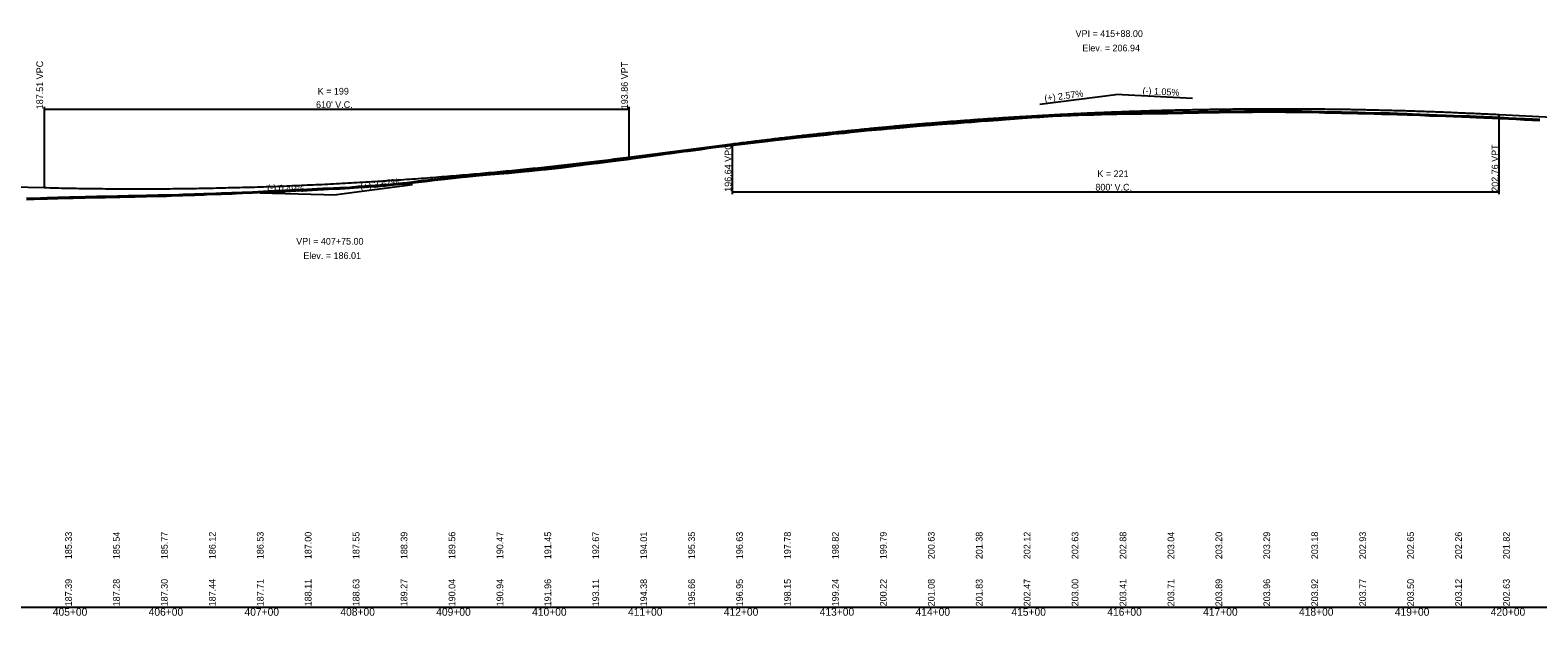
# Model space of a CAD drawing. Extents: x 1876258 to 1932803, y 754739 to 837911.
# Drawn here: x 1918819 to 1920391, y 827954 to 828565 of the extents above; entities that cross this region are included whole.
import ezdxf

# ---------------------------------------------------------------- set-up
doc = ezdxf.new("R2010")
doc.units = 0
for name, color, linetype in [('RD_DDB_GradeTX', 7, 'Continuous'), ('RD_DDB_Profile_EX', 7, 'Continuous'), ('RD_DDB_Profile_Lbl', 7, 'Continuous'), ('RD_DDB_Profile_PR', 7, 'Continuous'), ('RD_DDB_StaTX', 7, 'Continuous'), ('RD_DDB_StripGrade', 7, 'Continuous'), ('RD_DDB_VCLbl', 7, 'Continuous'), ('RD_GPK_Profile_Cell', 7, 'Continuous'), ('RD_Sketch1', 7, 'Continuous')]:
    doc.layers.add(name, color=color, linetype=linetype)

msp = doc.modelspace()

# ---------------------------------------------------------------- linework, layer by layer
at = {"layer": 'RD_DDB_GradeTX'}
for p, q in [((1919871.7, 828487.3), (1919951.1, 828497.5)), ((1920031, 828493.3), (1919951.1, 828497.5)), ((1919058.1, 828394.8), (1919138.1, 828392.9)), ((1919217.4, 828403.1), (1919138.1, 828392.9))]:
    msp.add_line(p, q, dxfattribs=at)
at = {"layer": 'RD_DDB_Profile_EX'}
for points in [[(1919426.8, 828428), (1919429.5, 828428.3), (1919443.7, 828430.2), (1919447.8, 828430.7), (1919460.7, 828432.5), (1919466, 828433.3), (1919478.1, 828435), (1919482.4, 828435.5), (1919486.2, 828436), (1919500.4, 828438), (1919504.9, 828438.5), (1919518.4, 828440.2), (1919526.1, 828441.4), (1919531.2, 828442.1), (1919543.6, 828443.6), (1919549.3, 828444.3), (1919561.3, 828445.8), (1919567.3, 828446.4), (1919578.9, 828447.8), (1919585.4, 828448.6), (1919596.1, 828449.9), (1919603, 828450.6), (1919614.4, 828451.8), (1919621.3, 828452.6), (1919632.2, 828453.7), (1919639.2, 828454.5), (1919649.9, 828455.5), (1919657.1, 828456.3), (1919667.7, 828457.3), (1919675, 828458.1), (1919685.4, 828459.1), (1919691.9, 828459.8), (1919701.4, 828460.7), (1919706.2, 828461.1), (1919712.5, 828461.7), (1919722.1, 828462.5), (1919729.6, 828463.1), (1919739.7, 828464.1), (1919747.2, 828464.7), (1919757.4, 828465.6), (1919765.1, 828466.1), (1919775.1, 828466.8), (1919782.8, 828467.4), (1919792.9, 828468.2), (1919800.4, 828468.7), (1919810.6, 828469.5), (1919818.2, 828470.1), (1919828.4, 828470.8), (1919836, 828471.5), (1919845.9, 828472.2), (1919853.7, 828472.8), (1919863.6, 828473.4), (1919871.8, 828474), (1919880.6, 828474.5), (1919885.5, 828474.8), (1919894.4, 828475.2), (1919904.1, 828475.7), (1919912, 828475.9), (1919920.8, 828476.2), (1919928.2, 828476.4), (1919936.1, 828476.7), (1919943, 828476.9), (1919952.3, 828477.1), (1919960.5, 828477.2), (1919969.9, 828477.3), (1919978.4, 828477.4), (1919987.6, 828477.5), (1919995.6, 828477.6), (1920005.2, 828477.8), (1920011.3, 828478), (1920020.9, 828478.1), (1920029.6, 828478.3), (1920037.4, 828478.5), (1920045.1, 828478.6), (1920051, 828478.6), (1920059, 828478.7), (1920067.3, 828478.9), (1920074.8, 828479), (1920085.5, 828479.2), (1920093.7, 828479.2), (1920102.7, 828479.3), (1920110.9, 828479.3), (1920119.9, 828479.3), (1920128.1, 828479.2), (1920137.1, 828479.1), (1920145.3, 828479), (1920155.2, 828478.9), (1920163.3, 828478.7), (1920169.3, 828478.5), (1920177.4, 828478.3), (1920186.4, 828478.1), (1920194.6, 828477.9), (1920203.7, 828477.7), (1920211.6, 828477.5), (1920220.6, 828477.3), (1920228.5, 828477.1), (1920236.6, 828476.9), (1920245.1, 828476.6), (1920254.9, 828476.3), (1920260.5, 828476.2), (1920268.6, 828475.8)], [(1920268.6, 828475.8), (1920278.4, 828475.4), (1920286.4, 828475.1), (1920295.3, 828474.8), (1920303.4, 828474.4), (1920312.2, 828474.1), (1920320.3, 828473.8), (1920326.9, 828473.6), (1920335.1, 828473.2), (1920343.8, 828472.8), (1920351.9, 828472.4), (1920360.7, 828472), (1920368.7, 828471.6), (1920377.6, 828471.2), (1920385.6, 828470.7), (1920393.3, 828470.3)], [(1918814.7, 828388), (1918822.9, 828388.2), (1918829.3, 828388.5), (1918836.7, 828388.7), (1918844.1, 828388.9), (1918847.6, 828389), (1918856.2, 828389.2), (1918859.5, 828389.4), (1918863.5, 828389.4), (1918871.9, 828389.6), (1918876, 828389.8), (1918884.6, 828389.9), (1918888.4, 828390.1), (1918896.7, 828390.2), (1918901.3, 828390.3), (1918909.8, 828390.5), (1918912.3, 828390.5), (1918920.8, 828390.7), (1918924.6, 828390.8), (1918927.7, 828390.8), (1918936.3, 828391), (1918939.8, 828391.1), (1918948.3, 828391.3), (1918952.2, 828391.4), (1918960.7, 828391.6), (1918965.7, 828391.7), (1918973.8, 828392), (1918977.9, 828392.2), (1918986.6, 828392.4), (1918990.2, 828392.6), (1918999.6, 828392.9), (1919002.8, 828393.1), (1919012.3, 828393.4), (1919018.2, 828393.6), (1919029.2, 828394), (1919033.6, 828394.1), (1919039.6, 828394.4), (1919050.6, 828394.9), (1919056.5, 828395.2), (1919067.5, 828395.6), (1919073.4, 828395.9), (1919084.3, 828396.4), (1919090.5, 828396.6), (1919101.3, 828397.2), (1919107.4, 828397.5), (1919118.2, 828398.1), (1919124.5, 828398.4), (1919135.1, 828399), (1919141.5, 828399.2), (1919152, 828399.7), (1919160.9, 828400.4), (1919167.5, 828400.8), (1919171.7, 828401.2), (1919178.7, 828401.6), (1919188.9, 828402.2), (1919193.9, 828402.8), (1919204, 828403.8), (1919207.4, 828404.2), (1919209.1, 828404.3), (1919217.4, 828405.2), (1919223.7, 828406.1), (1919233.5, 828407.1), (1919240.5, 828408), (1919251.2, 828409.3), (1919257.2, 828410), (1919269.1, 828411.2), (1919273.9, 828411.6), (1919287, 828412.9), (1919290.7, 828413.2), (1919298.7, 828413.9), (1919307.9, 828414.7), (1919317.9, 828415.5), (1919324.2, 828416), (1919334.4, 828417), (1919339.1, 828417.6), (1919352.1, 828418.9), (1919356.5, 828419.3), (1919372.4, 828421.1), (1919375, 828421.4), (1919377.6, 828421.7), (1919392.9, 828423.7), (1919393.5, 828423.8), (1919397.9, 828424.3), (1919409.9, 828425.8), (1919411.1, 828425.9), (1919426.8, 828428)]]:
    msp.add_lwpolyline(points, dxfattribs=at)
at = {"layer": 'RD_DDB_Profile_PR'}
for p, q in [((1920351.1, 828476.6), (1920799.1, 828453.2)), ((1919443.1, 828432.1), (1919551.1, 828446)), ((1917863.2, 828424.2), (1918833.1, 828400.4))]:
    msp.add_line(p, q, dxfattribs=at)
for points in [[(1919551.1, 828446), (1919567.1, 828448), (1919583.1, 828450), (1919599.1, 828451.9), (1919615.1, 828453.8), (1919631.1, 828455.6), (1919647.1, 828457.3), (1919663.1, 828459), (1919679.1, 828460.6), (1919695.1, 828462.2), (1919711.1, 828463.7), (1919727.1, 828465.2), (1919743.1, 828466.6), (1919759.1, 828467.9), (1919775.1, 828469.2), (1919791.1, 828470.4), (1919807.1, 828471.6), (1919823.1, 828472.7), (1919839.1, 828473.7), (1919855.1, 828474.7), (1919871.1, 828475.6), (1919887.1, 828476.5), (1919903.1, 828477.3), (1919919.1, 828478.1), (1919935.1, 828478.8), (1919951.1, 828479.4), (1919967.1, 828480), (1919983.1, 828480.5), (1919999.1, 828481), (1920015.1, 828481.4), (1920031.1, 828481.7), (1920047.1, 828482), (1920063.1, 828482.3), (1920079.1, 828482.4), (1920095.1, 828482.6), (1920111.1, 828482.6), (1920127.1, 828482.6), (1920143.1, 828482.6), (1920159.1, 828482.5), (1920175.1, 828482.3), (1920191.1, 828482.1), (1920207.1, 828481.8), (1920223.1, 828481.4), (1920239.1, 828481), (1920255.1, 828480.6), (1920271.1, 828480), (1920287.1, 828479.5), (1920303.1, 828478.8), (1920319.1, 828478.1), (1920335.1, 828477.4), (1920351.1, 828476.6)], [(1918833.1, 828400.4), (1918845.3, 828400.1), (1918857.5, 828399.8), (1918869.7, 828399.6), (1918881.9, 828399.5), (1918894.1, 828399.3), (1918906.3, 828399.2), (1918918.5, 828399.2), (1918930.7, 828399.2), (1918942.9, 828399.2), (1918955.1, 828399.2), (1918967.3, 828399.3), (1918979.5, 828399.5), (1918991.7, 828399.6), (1919003.9, 828399.8), (1919016.1, 828400.1), (1919028.3, 828400.4), (1919040.5, 828400.7), (1919052.7, 828401), (1919064.9, 828401.4), (1919077.1, 828401.8), (1919089.3, 828402.3), (1919101.5, 828402.8), (1919113.7, 828403.4), (1919125.9, 828403.9), (1919138.1, 828404.6), (1919150.3, 828405.2), (1919162.5, 828405.9), (1919174.7, 828406.6), (1919186.9, 828407.4), (1919199.1, 828408.2), (1919211.3, 828409), (1919223.5, 828409.9), (1919235.7, 828410.8), (1919247.9, 828411.8), (1919260.1, 828412.8), (1919272.3, 828413.8), (1919284.5, 828414.9), (1919296.7, 828416), (1919308.9, 828417.1), (1919321.1, 828418.3), (1919333.3, 828419.5), (1919345.5, 828420.8), (1919357.7, 828422), (1919369.9, 828423.4), (1919382.1, 828424.7), (1919394.3, 828426.1), (1919406.5, 828427.6), (1919418.7, 828429.1), (1919430.9, 828430.6), (1919443.1, 828432.1)]]:
    msp.add_spline(points, degree=3, dxfattribs=at)
at = {"layer": 'RD_DDB_VCLbl'}
for p, q in [((1918833.1, 828484.6), (1918833.1, 828400.4)), ((1919443.1, 828484.6), (1919443.1, 828432.1)), ((1918833.1, 828482.1), (1919443.1, 828482.1)), ((1920351.1, 828393.5), (1920351.1, 828476.6)), ((1919551.1, 828393.5), (1919551.1, 828446)), ((1919551.1, 828396), (1920351.1, 828396))]:
    msp.add_line(p, q, dxfattribs=at)
at = {"layer": 'RD_GPK_Profile_Cell'}
msp.add_line((1878363.1, 827962.8), (1926563.1, 827962.8), dxfattribs=at)
at = {"layer": 'RD_Sketch1'}
msp.add_lwpolyline([(1918814.6, 828389.2), (1918822.8, 828389.5), (1918829.3, 828389.7), (1918836.6, 828390), (1918836.6, 828390), (1918844, 828390.2), (1918847.5, 828390.3), (1918856.1, 828390.5), (1918859.5, 828390.6), (1918863.5, 828390.7), (1918871.9, 828390.9), (1918876, 828391), (1918884.5, 828391.2), (1918888.3, 828391.3), (1918896.7, 828391.5), (1918901.3, 828391.5), (1918909.8, 828391.7), (1918912.2, 828391.7), (1918920.7, 828392), (1918924.6, 828392), (1918927.7, 828392.1), (1918936.3, 828392.2), (1918939.8, 828392.4), (1918948.3, 828392.5), (1918952.2, 828392.7), (1918960.6, 828392.8), (1918965.7, 828393), (1918973.8, 828393.3), (1918977.9, 828393.4), (1918986.5, 828393.7), (1918990.1, 828393.9), (1918999.6, 828394.2), (1919002.7, 828394.3), (1919012.3, 828394.6), (1919018.1, 828394.8), (1919029.1, 828395.3), (1919033.6, 828395.4), (1919039.6, 828395.7), (1919050.5, 828396.1), (1919056.4, 828396.4), (1919067.4, 828396.9), (1919073.4, 828397.2), (1919084.3, 828397.7), (1919090.4, 828397.9), (1919101.2, 828398.4), (1919107.3, 828398.7), (1919118.1, 828399.3), (1919124.4, 828399.7), (1919135, 828400.2), (1919141.5, 828400.4), (1919151.9, 828401), (1919160.8, 828401.7), (1919167.4, 828402.1), (1919171.6, 828402.4), (1919178.6, 828402.8), (1919188.8, 828403.5), (1919193.8, 828404), (1919203.9, 828405), (1919207.3, 828405.4), (1919209, 828405.5), (1919217.2, 828406.5), (1919223.6, 828407.4), (1919233.3, 828408.4), (1919240.3, 828409.2), (1919251.1, 828410.6), (1919257.1, 828411.2), (1919269, 828412.5), (1919273.8, 828412.9), (1919286.9, 828414.2), (1919290.6, 828414.5), (1919298.6, 828415.1), (1919307.8, 828416), (1919317.8, 828416.8), (1919324.1, 828417.2), (1919334.3, 828418.3), (1919338.9, 828418.8), (1919352, 828420.2), (1919356.3, 828420.6), (1919372.3, 828422.3), (1919374.9, 828422.7), (1919377.5, 828423), (1919392.7, 828424.9), (1919393.3, 828425), (1919397.7, 828425.5), (1919409.7, 828427), (1919410.9, 828427.1), (1919426.6, 828429.2), (1919429.3, 828429.5), (1919443.5, 828431.4), (1919447.6, 828431.9), (1919460.5, 828433.7), (1919465.8, 828434.5), (1919477.9, 828436.2), (1919482.2, 828436.7), (1919486, 828437.2), (1919500.2, 828439.2), (1919504.7, 828439.8), (1919518.2, 828441.4), (1919525.9, 828442.6), (1919531, 828443.4), (1919543.5, 828444.9), (1919549.1, 828445.6), (1919561.1, 828447), (1919567.2, 828447.7), (1919578.7, 828449.1), (1919585.2, 828449.9), (1919596, 828451.1), (1919602.8, 828451.9), (1919614.2, 828453.1), (1919621.2, 828453.9), (1919632, 828455), (1919639.1, 828455.7), (1919649.8, 828456.8), (1919657, 828457.5), (1919667.5, 828458.6), (1919674.9, 828459.3), (1919685.3, 828460.3), (1919691.8, 828461), (1919701.3, 828461.9), (1919706.1, 828462.4), (1919712.4, 828462.9), (1919722, 828463.8), (1919729.5, 828464.4), (1919739.6, 828465.3), (1919747.1, 828465.9), (1919757.3, 828466.8), (1919765, 828467.3), (1919775, 828468), (1919782.7, 828468.7), (1919792.8, 828469.5), (1919800.3, 828470), (1919810.5, 828470.8), (1919818.1, 828471.4), (1919828.3, 828472.1), (1919835.9, 828472.7), (1919845.9, 828473.4), (1919853.6, 828474), (1919863.5, 828474.7), (1919871.7, 828475.2), (1919880.6, 828475.8), (1919885.5, 828476), (1919894.4, 828476.4), (1919904.1, 828476.9), (1919912, 828477.2), (1919920.8, 828477.4), (1919928.1, 828477.7), (1919936.1, 828477.9), (1919943, 828478.1), (1919952.3, 828478.3), (1919960.5, 828478.4), (1919969.9, 828478.5), (1919978.3, 828478.7), (1919987.6, 828478.8), (1919995.5, 828478.9), (1920005.1, 828479.1), (1920011.3, 828479.2), (1920020.9, 828479.4), (1920029.6, 828479.5), (1920037.3, 828479.7), (1920045.1, 828479.9), (1920051, 828479.9), (1920059, 828480), (1920067.3, 828480.1), (1920074.8, 828480.2), (1920085.5, 828480.4), (1920093.7, 828480.5), (1920102.7, 828480.5), (1920110.9, 828480.5), (1920119.9, 828480.5), (1920128.1, 828480.5), (1920137.1, 828480.4), (1920145.3, 828480.3), (1920155.2, 828480.1), (1920163.3, 828479.9), (1920169.3, 828479.8), (1920177.4, 828479.5), (1920186.4, 828479.3), (1920194.6, 828479.1), (1920203.7, 828478.9), (1920211.7, 828478.7), (1920220.6, 828478.5), (1920228.5, 828478.3), (1920236.6, 828478.2), (1920245.1, 828477.9), (1920255, 828477.6), (1920260.5, 828477.4), (1920268.7, 828477.1), (1920278.5, 828476.6), (1920286.5, 828476.3), (1920295.4, 828476), (1920303.4, 828475.7), (1920312.2, 828475.4), (1920320.3, 828475.1), (1920327, 828474.9), (1920335.1, 828474.5), (1920343.8, 828474.1), (1920351.9, 828473.7), (1920360.7, 828473.3), (1920368.8, 828472.9), (1920377.7, 828472.4), (1920385.7, 828472), (1920393.3, 828471.6)], dxfattribs=at)

# ---------------------------------------------------------------- texts
at = {"layer": 'RD_DDB_GradeTX'}
for s, rotation, p in [('(+) 2.57%', 7.3335, (1919877.1, 828490)), ('(-) 1.05%', 357.008, (1919978.8, 828498)), ('(+) 2.57%', 7.3335, (1919163.3, 828398.1)), ('(-) 0.49%', 358.5922, (1919065.8, 828396.6))]:
    msp.add_text(s, height=7, rotation=rotation, dxfattribs=at).set_placement(p)
at = {"layer": 'RD_DDB_Profile_Lbl'}
for s, p in [('VPI = 415+88.00', (1919909.1, 828557.5)), ('Elev. = 206.94', (1919916.2, 828542.5)), ('VPI = 407+75.00', (1919096.1, 828340.9)), ('Elev. = 186.01', (1919103.6, 828325.9))]:
    msp.add_text(s, height=7, dxfattribs=at).set_placement(p)
at = {"layer": 'RD_DDB_StaTX'}
for s, p in [('405+00', (1918842.2, 827953.8)), ('406+00', (1918942.2, 827953.8)), ('407+00', (1919042.2, 827953.8)), ('408+00', (1919142.2, 827953.8)), ('409+00', (1919242.2, 827953.8)), ('410+00', (1919342.2, 827953.8)), ('411+00', (1919442.2, 827953.8)), ('412+00', (1919542.2, 827953.8)), ('413+00', (1919642.2, 827953.8)), ('414+00', (1919742.2, 827953.8)), ('415+00', (1919842.2, 827953.8)), ('416+00', (1919942.2, 827953.8)), ('417+00', (1920042.2, 827953.8)), ('418+00', (1920142.2, 827953.8)), ('419+00', (1920242.2, 827953.8)), ('420+00', (1920342.2, 827953.8))]:
    msp.add_text(s, height=8, dxfattribs=at).set_placement(p)
at = {"layer": 'RD_DDB_StripGrade'}
for s, p in [('187.51 VPC', (1918832.1, 828482.1)), ('193.86 VPT', (1919442.1, 828482.1)), ('196.64 VPC', (1919550.1, 828396)), ('202.76 VPT', (1920350.1, 828396)), ('185.33', (1918862.1, 828012.8)), ('185.54', (1918912.1, 828012.8)), ('185.77', (1918962.1, 828012.8)), ('186.12', (1919012.1, 828012.8)), ('186.53', (1919062.1, 828012.8)), ('187.00', (1919112.1, 828012.8)), ('187.55', (1919162.1, 828012.8)), ('188.39', (1919212.1, 828012.8)), ('189.56', (1919262.1, 828012.8)), ('190.47', (1919312.1, 828012.8)), ('191.45', (1919362.1, 828012.8)), ('192.67', (1919412.1, 828012.8)), ('194.01', (1919462.1, 828012.8)), ('195.35', (1919512.1, 828012.8)), ('196.63', (1919562.1, 828012.8)), ('197.78', (1919612.1, 828012.8)), ('198.82', (1919662.1, 828012.8)), ('199.79', (1919712.1, 828012.8)), ('200.63', (1919762.1, 828012.8)), ('201.38', (1919812.1, 828012.8)), ('202.12', (1919862.1, 828012.8)), ('202.63', (1919912.1, 828012.8)), ('202.88', (1919962.1, 828012.8)), ('203.04', (1920012.1, 828012.8)), ('203.20', (1920062.1, 828012.8)), ('203.29', (1920112.1, 828012.8)), ('203.18', (1920162.1, 828012.8)), ('202.93', (1920212.1, 828012.8)), ('202.65', (1920262.1, 828012.8)), ('202.26', (1920312.1, 828012.8)), ('201.82', (1920362.1, 828012.8)), ('187.39', (1918862.1, 827963.6)), ('187.28', (1918912.1, 827963.6)), ('187.30', (1918962.1, 827963.6)), ('187.44', (1919012.1, 827963.6)), ('187.71', (1919062.1, 827963.6)), ('188.11', (1919112.1, 827963.6)), ('188.63', (1919162.1, 827963.6)), ('189.27', (1919212.1, 827963.6)), ('190.04', (1919262.1, 827963.6)), ('190.94', (1919312.1, 827963.6)), ('191.96', (1919362.1, 827963.6)), ('193.11', (1919412.1, 827963.6)), ('194.38', (1919462.1, 827963.6)), ('195.66', (1919512.1, 827963.6)), ('196.95', (1919562.1, 827963.6)), ('198.15', (1919612.1, 827963.6)), ('199.24', (1919662.1, 827963.6)), ('200.22', (1919712.1, 827963.6)), ('201.08', (1919762.1, 827963.6)), ('201.83', (1919812.1, 827963.6)), ('202.47', (1919862.1, 827963.6)), ('203.00', (1919912.1, 827963.6)), ('203.41', (1919962.1, 827963.6)), ('203.71', (1920012.1, 827963.6)), ('203.89', (1920062.1, 827963.6)), ('203.96', (1920112.1, 827963.6)), ('203.92', (1920162.1, 827963.6)), ('203.77', (1920212.1, 827963.6)), ('203.50', (1920262.1, 827963.6)), ('203.12', (1920312.1, 827963.6)), ('202.63', (1920362.1, 827963.6))]:
    msp.add_text(s, height=7, rotation=90, dxfattribs=at).set_placement(p)
at = {"layer": 'RD_DDB_VCLbl'}
for s, p in [('K = 199', (1919118.5, 828497.4)), ("610' V.C.", (1919116.8, 828483.4)), ("800' V.C.", (1919929.8, 828397.3)), ('K = 221', (1919931.9, 828411.3))]:
    msp.add_text(s, height=7, dxfattribs=at).set_placement(p)

doc.saveas('drawing.dxf')
